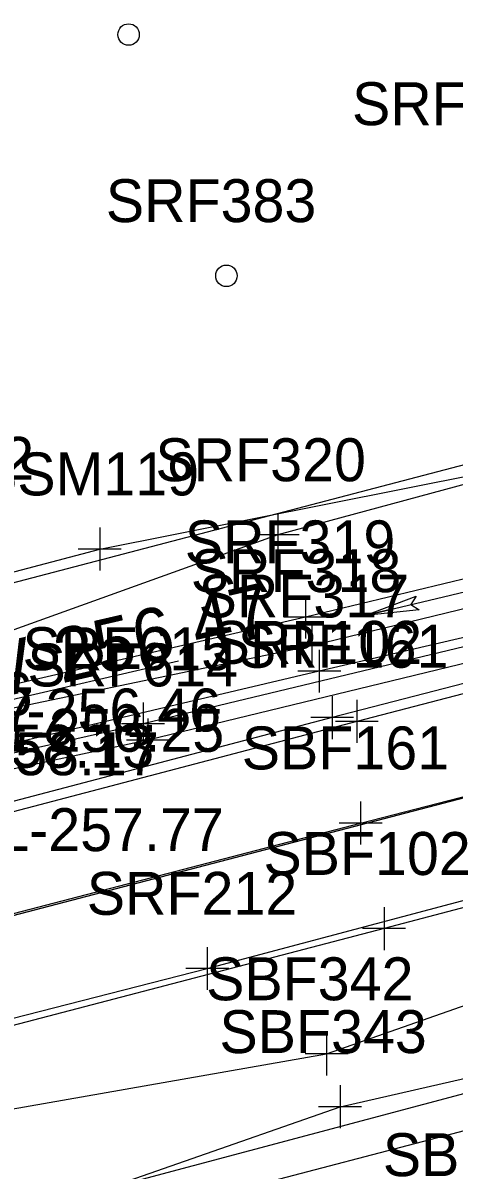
# Model space of a CAD drawing. Extents: x 818717 to 846077, y 440014 to 541392.
# Drawn here: x 832262 to 832302.2, y 493229.4 to 493336.2 of the extents above; entities that cross this region are included whole.
import ezdxf

# ---------------------------------------------------------------- set-up
doc = ezdxf.new("R2010")
doc.units = 0
for name, color, linetype in [('SURVEY - CENTERLINE - Preliminary', 7, 'Continuous'), ('SURVEY - DRAINAGE - Area Shapes', 7, 'Continuous'), ('SURVEY - DRAINAGE - Natural Features Text', 7, 'Continuous'), ('SURVEY - DRAINAGE - Pipes and Culverts Text', 7, 'Continuous'), ('SURVEY - DTM - Breaklines', 7, 'Continuous'), ('SURVEY - DTM - Breaklines - Points - Elevations', 7, 'Continuous'), ('SURVEY - DTM - Breaklines - Points - Locators', 7, 'Continuous'), ('SURVEY - DTM - Breaklines - Points - Numbers', 7, 'Continuous'), ('SURVEY - DTM - Spot Points - Locators', 7, 'Continuous'), ('SURVEY - DTM - Spot Points - Point Numbers', 7, 'Continuous'), ('SURVEY - PROPERTY - ROW Lines', 7, 'Continuous'), ('SURVEY - TRAFFIC CONTROL - Pavement Marking - Points - Locators', 7, 'Continuous'), ('SURVEY - TRAFFIC CONTROL - Pavement Marking - Points - Numbers', 7, 'Continuous'), ('SURVEY - TRAFFIC CONTROL - Pavement Marking with Text', 7, 'Continuous'), ('SURVEY - TRANSPORTATION - Features - Points - Elevations', 7, 'Continuous'), ('SURVEY - TRANSPORTATION - Roads', 7, 'Continuous'), ('SURVEY - TRANSPORTATION - Roads - Points - Locators', 7, 'Continuous'), ('SURVEY - TRANSPORTATION - Roads - Points - Numbers', 7, 'Continuous'), ('SURVEY - UTILITIES - Electric (Overhead) with Text', 7, 'Continuous'), ('SURVEY - UTILITIES - Telephone (Underground) - Points - Locators', 7, 'Continuous'), ('SURVEY - UTILITIES - Telephone (Underground) - Points - Numbers', 7, 'Continuous'), ('SURVEY - UTILITIES - Telephone (Underground) with Text', 7, 'Continuous'), ('SURVEY - UTILITIES - Water - Points - Locators', 7, 'Continuous'), ('SURVEY - UTILITIES - Water - Points - Numbers', 7, 'Continuous'), ('SURVEY - UTILITIES - Water with Text', 7, 'Continuous')]:
    doc.layers.add(name, color=color, linetype=linetype)

msp = doc.modelspace()

# ---------------------------------------------------------------- linework, layer by layer
at = {"layer": 'SURVEY - CENTERLINE - Preliminary'}
msp.add_line((832177.83, 493231.34), (832536.48, 493325), dxfattribs=at)
msp.add_line((832177.83, 493231.34), (832536.48, 493325), dxfattribs=at)
msp.add_line((832177.83, 493231.34), (832536.48, 493325), dxfattribs=at)
at = {"layer": 'SURVEY - DRAINAGE - Area Shapes'}
msp.add_lwpolyline([(833331.86, 493535.43), (832825.85, 493400.54), (832121.68, 493216.64), (831495.16, 493049.75), (830960.37, 492909.24), (830124.73, 492686.08), (830069.9, 493396.23), (830870.86, 494031.84), (831248.11, 494413.67), (831536.95, 494545.33), (832050.07, 494534.01), (832097.96, 494614.84), (832139.36, 494784.62), (832167.46, 494840.58), (832274.31, 494844.36), (832647.22, 494804.13), (832934.24, 494910.41), (833081.03, 494456.05), (833331.86, 493535.43)], dxfattribs=at)
at = {"layer": 'SURVEY - DRAINAGE - Natural Features Text'}
for p, q in [((832293.9, 493281), (832322.11, 493287.74)), ((832296.53, 493281.63), (832293.9, 493281)), ((832256.74, 493272.21), (832276.5, 493276.8))]:
    msp.add_line(p, q, dxfattribs=at)
msp.add_lwpolyline([(832293.9, 493281), (832298.66, 493282.81), (832298.18, 493282.03), (832298.96, 493281.54)], close=True, dxfattribs=at)
msp.add_lwpolyline([(832293.9, 493281), (832298.66, 493282.81), (832298.18, 493282.03), (832298.96, 493281.54), (832293.9, 493281)], dxfattribs=at)
at = {"layer": 'SURVEY - DTM - Breaklines'}
for points in [[(832331.98, 493301), (832285.77, 493288.52), (832242.73, 493273.08), (832244.99, 493268.14)], [(832334.78, 493292.05), (832288.36, 493280.87), (832250.8, 493272.21)], [(832335.47, 493289.5), (832288.94, 493278.19), (832251.09, 493270.32)], [(832336.24, 493286.66), (832289.63, 493275.83), (832250.76, 493266.66), (832244.56, 493268.84)], [(831770.96, 493123.4), (831813.86, 493135.07), (831857.39, 493146.73), (831900.86, 493158.47), (831946.48, 493170.59), (831992.71, 493182.98), (832039.15, 493195.18), (832084.76, 493206.97), (832129.99, 493218.78), (832149.29, 493223.98), (832194.39, 493235.62), (832247.61, 493249.75), (832293.49, 493261.68), (832340.52, 493273.78)], [(832195.49, 493218.96), (832241.6, 493231.67), (832290.32, 493240.18), (832343.91, 493258.96)], [(832151.95, 493201.02), (832196.78, 493208.44), (832246.16, 493219.41), (832291.57, 493235.26), (832344.85, 493247.44)]]:
    msp.add_lwpolyline(points, dxfattribs=at)
at = {"layer": 'SURVEY - DTM - Breaklines - Points - Locators'}
for p, q in [((832285.77, 493290.52), (832285.77, 493286.52)), ((832287.77, 493288.52), (832283.77, 493288.52)), ((832288.36, 493282.87), (832288.36, 493278.87)), ((832290.36, 493280.87), (832286.36, 493280.87)), ((832288.94, 493280.19), (832288.94, 493276.19)), ((832290.94, 493278.19), (832286.94, 493278.19)), ((832289.63, 493277.83), (832289.63, 493273.83)), ((832291.63, 493275.83), (832287.63, 493275.83)), ((832293.49, 493263.68), (832293.49, 493259.68)), ((832295.49, 493261.68), (832291.49, 493261.68)), ((832290.32, 493242.18), (832290.32, 493238.18)), ((832292.32, 493240.18), (832288.32, 493240.18)), ((832291.57, 493237.26), (832291.57, 493233.26)), ((832293.57, 493235.26), (832289.57, 493235.26))]:
    msp.add_line(p, q, dxfattribs=at)
at = {"layer": 'SURVEY - DTM - Spot Points - Locators'}
for centre in [(832271.86, 493335.12), (832280.98, 493312.65)]:
    msp.add_circle(centre, 1, dxfattribs=at)
at = {"layer": 'SURVEY - PROPERTY - ROW Lines'}
for p, q in [((832170.25, 493260.36), (832528.9, 493354.02)), ((832185.41, 493202.31), (832544.06, 493295.97))]:
    msp.add_line(p, q, dxfattribs=at)
at = {"layer": 'SURVEY - TRAFFIC CONTROL - Pavement Marking - Points - Locators'}
for p, q in [((832293.14, 493273.15), (832293.14, 493269.15)), ((832295.14, 493271.15), (832291.14, 493271.15)), ((832279.2, 493250.14), (832279.2, 493246.14)), ((832281.2, 493248.14), (832277.2, 493248.14))]:
    msp.add_line(p, q, dxfattribs=at)
at = {"layer": 'SURVEY - TRAFFIC CONTROL - Pavement Marking with Text'}
for points in [[(832337.33, 493282.63), (832293.14, 493271.15), (832248.41, 493259.42), (832203.01, 493247.2), (832159.39, 493235.77), (832116.7, 493224.52)], [(832086.82, 493197.77), (832134.83, 493210.3), (832182.8, 493222.89), (832231.22, 493235.87), (832279.2, 493248.14), (832327.01, 493260.84), (832342.88, 493265)]]:
    msp.add_lwpolyline(points, dxfattribs=at)
at = {"layer": 'SURVEY - TRANSPORTATION - Roads'}
for points in [[(832337.43, 493283.54), (832290.84, 493271.51), (832245.1, 493259.5), (832196.72, 493246.64), (832147.48, 493233.5), (832099.04, 493220.81), (832050.97, 493208.2), (832002.93, 493195.99), (831956.8, 493183.74), (831911.55, 493171.73), (831864.83, 493159.08), (831817.3, 493145.76), (831768.68, 493132.69)], [(832342.92, 493264.27), (832295.67, 493251.85), (832250.01, 493239.95), (832200.63, 493227.05), (832152.17, 493214.17), (832103.93, 493201.62), (832054.77, 493188.77), (832008.06, 493176.05), (831961.15, 493163.88), (831914.15, 493151.63), (831865.83, 493138.65), (831819.22, 493125.71), (831773.59, 493113.35)]]:
    msp.add_lwpolyline(points, dxfattribs=at)
at = {"layer": 'SURVEY - TRANSPORTATION - Roads - Points - Locators'}
for p, q in [((832290.84, 493273.51), (832290.84, 493269.51)), ((832292.84, 493271.51), (832288.84, 493271.51)), ((832295.67, 493253.85), (832295.67, 493249.85)), ((832297.67, 493251.85), (832293.67, 493251.85))]:
    msp.add_line(p, q, dxfattribs=at)
at = {"layer": 'SURVEY - UTILITIES - Electric (Overhead) with Text'}
msp.add_lwpolyline([(832667.18, 493331.74), (832415.28, 493266.23), (832147.85, 493195.27), (831907.96, 493131.64), (831666.03, 493064.14), (831375.19, 492986.65), (831101.3, 492913.04)], dxfattribs=at)
at = {"layer": 'SURVEY - UTILITIES - Telephone (Underground) - Points - Locators'}
for p, q in [((832273.21, 493272.92), (832273.21, 493268.92)), ((832273.67, 493271.41), (832273.67, 493267.41)), ((832275.21, 493270.92), (832271.21, 493270.92)), ((832275.67, 493269.41), (832271.67, 493269.41))]:
    msp.add_line(p, q, dxfattribs=at)
at = {"layer": 'SURVEY - UTILITIES - Telephone (Underground) with Text'}
for points in [[(832336.35, 493286.08), (832273.21, 493270.92), (832254.63, 493266.72), (832240.89, 493262), (832221.1, 493257.02), (832218.04, 493259.29), (832215.04, 493268.96)], [(832336.84, 493284.72), (832273.67, 493269.41), (832254.65, 493265.33), (832241.32, 493260.67), (832203.09, 493249.29), (832136.87, 493232.13), (832079.02, 493217.89), (831981.8, 493192.44), (831904.38, 493171.41), (831843.31, 493154.78), (831799.38, 493142.99), (831790.74, 493148.24), (831757.75, 493149.99)]]:
    msp.add_lwpolyline(points, dxfattribs=at)
at = {"layer": 'SURVEY - UTILITIES - Water - Points - Locators'}
for p, q in [((832269.17, 493289.2), (832269.17, 493285.2)), ((832271.17, 493287.2), (832267.17, 493287.2))]:
    msp.add_line(p, q, dxfattribs=at)
at = {"layer": 'SURVEY - UTILITIES - Water with Text'}
msp.add_lwpolyline([(831168.53, 492982.83), (831221.68, 492997.59), (831271.35, 493010.03), (831320.05, 493023.02), (831382.11, 493039.09), (831464.43, 493059.02), (831521.6, 493075.98), (831637.27, 493105.47), (831699.54, 493130.69), (831734.63, 493142.29), (831763.92, 493149.4), (831800.53, 493157.83), (831844.47, 493169.57), (831878.73, 493177.18), (831933.72, 493193.59), (832000.95, 493211.25), (832058.59, 493225.48), (832113.6, 493238.29), (832172.68, 493261.93), (832217.98, 493273.66), (832269.17, 493287.2), (832330.79, 493299.45)], dxfattribs=at)

# ---------------------------------------------------------------- texts
at = {"layer": 'SURVEY - DRAINAGE - Pipes and Culverts Text'}
msp.add_text('INV-256.47', height=5, rotation=12.9632, dxfattribs=at).set_placement((832252.58, 493271.68))
at = {"layer": 'SURVEY - DTM - Breaklines - Points - Elevations'}
for s, p in [('EL-256.46', (832255.8, 493270.21)), ('EL-256.25', (832256.09, 493268.32)), ('EL-258.13', (832249.56, 493266.84)), ('EL-258.17', (832249.99, 493266.14))]:
    msp.add_text(s, height=4, dxfattribs=at).set_placement(p)
at = {"layer": 'SURVEY - DTM - Breaklines - Points - Numbers'}
for s, p in [('SRF320', (832274.36, 493293.52)), ('SRF319', (832277.1, 493285.87)), ('SRF318', (832277.66, 493283.19)), ('SRF317', (832278.39, 493280.83)), ('SBF161', (832282.41, 493266.68)), ('SBF342', (832279.09, 493245.18)), ('SBF343', (832280.33, 493240.26)), ('SBF349', (832295.56, 493228.8))]:
    msp.add_text(s, height=4, dxfattribs=at).set_placement(p)
at = {"layer": 'SURVEY - DTM - Spot Points - Point Numbers'}
for s, p in [('SRF387', (832292.69, 493326.68)), ('SRF383', (832269.74, 493317.65)), ('SRF382', (832243.43, 493293.65))]:
    msp.add_text(s, height=4, dxfattribs=at).set_placement(p)
at = {"layer": 'SURVEY - TRAFFIC CONTROL - Pavement Marking - Points - Numbers'}
for s, p in [('SRF161', (832282.05, 493276.15)), ('SRF212', (832267.96, 493253.14))]:
    msp.add_text(s, height=4, dxfattribs=at).set_placement(p)
at = {"layer": 'SURVEY - TRANSPORTATION - Features - Points - Elevations'}
msp.add_text('EL-257.77', height=4, dxfattribs=at).set_placement((832256.05, 493259.07))
at = {"layer": 'SURVEY - TRANSPORTATION - Roads - Points - Numbers'}
for s, p in [('SRF102', (832279.6, 493276.51)), ('SBF102', (832284.43, 493256.85))]:
    msp.add_text(s, height=4, dxfattribs=at).set_placement(p)
at = {"layer": 'SURVEY - UTILITIES - Telephone (Underground) - Points - Numbers'}
for s, p in [('SRF615', (832261.97, 493275.92)), ('SRF614', (832262.43, 493274.41)), ('SRF616', (832243.28, 493271.72)), ('SRF617', (832243.41, 493270.33))]:
    msp.add_text(s, height=4, dxfattribs=at).set_placement(p)
at = {"layer": 'SURVEY - UTILITIES - Water - Points - Numbers'}
msp.add_text('SSM119', height=4, dxfattribs=at).set_placement((832257.92, 493292.2))

doc.saveas('drawing.dxf')
